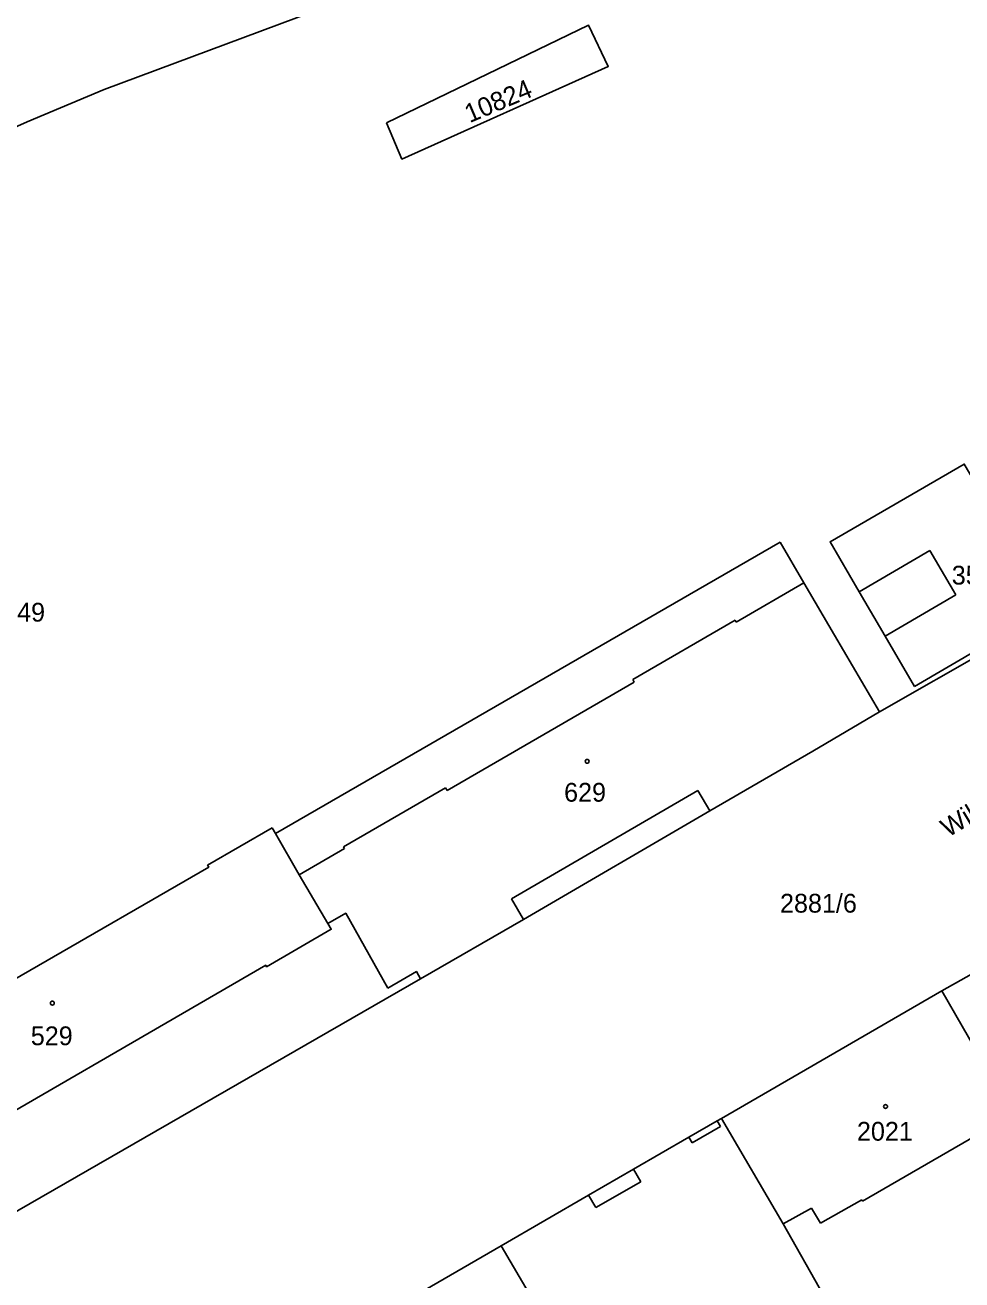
# Model space of a CAD drawing. Extents: x -564952 to -564307, y -1202373 to -1201847.
# Drawn here: x -564730.1 to -564645.4, y -1202200.5 to -1202086.9 of the extents above; entities that cross this region are included whole.
import ezdxf

# ---------------------------------------------------------------- set-up
doc = ezdxf.new("R2010")
doc.units = 0
for name, color, linetype in [('Hranice parcel', 7, 'Continuous'), ('Parcelní čísla', 7, 'Continuous'), ('Pop  PČ popisy', 7, 'Continuous'), ('Vnitřní kresba', 7, 'Continuous'), ('Značky budov', 7, 'Continuous')]:
    doc.layers.add(name, color=color, linetype=linetype)

msp = doc.modelspace()

# ---------------------------------------------------------------- linework, layer by layer
at = {"layer": 'Hranice parcel'}
for p, q in [((-564707.49, -1202160.1), (-564661.83, -1202133.72)), ((-564634.78, -1202138.78), (-564652.84, -1202149.09)), ((-564656.9, -1202142.15), (-564652.84, -1202149.09)), ((-564652.84, -1202149.09), (-564658.86, -1202152.65)), ((-564707.79, -1202159.58), (-564707.49, -1202160.1)), ((-564647.18, -1202174.34), (-564629.78, -1202164.5)), ((-564667.14, -1202185.87), (-564647.18, -1202174.34)), ((-564667.14, -1202185.87), (-564661.56, -1202195.43)), ((-564694.52, -1202201.73), (-564687.07, -1202197.41))]:
    msp.add_line(p, q, dxfattribs=at)
for points in [[(-564637.69, -1202058.81), (-564638.03, -1202059.06), (-564655, -1202066.79), (-564662.43, -1202069.69), (-564704.06, -1202085.69), (-564722.99, -1202092.74), (-564729.95, -1202095.67), (-564736.84, -1202098.72), (-564741.32, -1202100.95), (-564768.52, -1202116.71), (-564777.25, -1202121.88), (-564783.74, -1202125.64), (-564785.97, -1202126.79), (-564816.39, -1202144.49)], [(-564697.44, -1202095.78), (-564679.17, -1202086.93), (-564677.37, -1202090.67), (-564696.04, -1202099.05), (-564697.44, -1202095.78)], [(-564649.66, -1202146.78), (-564652.32, -1202142.22), (-564654.66, -1202138.21), (-564657.3, -1202133.69), (-564645.16, -1202126.66), (-564637.48, -1202139.67), (-564649.66, -1202146.78)], [(-564661.83, -1202133.72), (-564659.67, -1202137.41), (-564656.9, -1202142.15)], [(-564658.86, -1202152.65), (-564668.19, -1202158.04), (-564685.03, -1202167.87), (-564694.35, -1202173.24)], [(-564746.42, -1202194.29), (-564751.8, -1202185.07), (-564746.02, -1202181.72), (-564745.95, -1202181.85), (-564713.53, -1202163.13), (-564713.63, -1202162.96), (-564707.79, -1202159.58)], [(-564702.76, -1202168.23), (-564705.33, -1202163.82), (-564707.49, -1202160.1)], [(-564746.42, -1202194.29), (-564740.54, -1202190.88), (-564740.63, -1202190.71), (-564708.37, -1202172.01), (-564708.29, -1202172.15), (-564702.44, -1202168.76), (-564702.76, -1202168.23)], [(-564702.76, -1202168.23), (-564701.13, -1202167.31), (-564697.31, -1202174.08)], [(-564697.31, -1202174.08), (-564694.74, -1202172.59), (-564694.35, -1202173.24)], [(-564694.35, -1202173.24), (-564735.89, -1202197.13), (-564730.32, -1202210.59), (-564747.11, -1202220.56)], [(-564647.18, -1202174.34), (-564641.67, -1202183.91), (-564640.9, -1202185.58), (-564639.75, -1202188.35)], [(-564687.07, -1202197.41), (-564679.15, -1202192.82), (-564675.09, -1202190.47), (-564670.07, -1202187.57), (-564667.53, -1202186.1), (-564667.14, -1202185.87)], [(-564661.56, -1202195.43), (-564657.9, -1202201.87), (-564654.13, -1202208.52)], [(-564675.55, -1202217.24), (-564682.1, -1202205.88), (-564687.07, -1202197.41)]]:
    msp.add_lwpolyline(points, dxfattribs=at)
at = {"layer": 'Vnitřní kresba'}
for p, q in [((-564654.66, -1202138.21), (-564648.27, -1202134.48)), ((-564648.27, -1202134.48), (-564645.93, -1202138.49)), ((-564659.67, -1202137.41), (-564665.8, -1202140.95)), ((-564645.93, -1202138.49), (-564652.32, -1202142.22)), ((-564665.9, -1202140.78), (-564675.16, -1202146.16)), ((-564665.8, -1202140.95), (-564665.9, -1202140.78)), ((-564675.02, -1202146.39), (-564691.95, -1202156.19)), ((-564675.16, -1202146.16), (-564675.02, -1202146.39)), ((-564692.09, -1202155.95), (-564701.33, -1202161.3)), ((-564691.95, -1202156.19), (-564692.09, -1202155.95)), ((-564669.27, -1202156.19), (-564686.12, -1202166.01)), ((-564668.19, -1202158.04), (-564669.27, -1202156.19)), ((-564701.24, -1202161.46), (-564705.33, -1202163.82)), ((-564701.33, -1202161.3), (-564701.24, -1202161.46)), ((-564686.12, -1202166.01), (-564685.03, -1202167.87)), ((-564667.23, -1202186.62), (-564667.53, -1202186.1)), ((-564654.37, -1202193.36), (-564640.9, -1202185.58)), ((-564670.07, -1202187.57), (-564669.77, -1202188.09)), ((-564669.77, -1202188.09), (-564667.23, -1202186.62)), ((-564674.44, -1202191.6), (-564675.09, -1202190.47)), ((-564678.49, -1202193.95), (-564674.44, -1202191.6)), ((-564679.15, -1202192.82), (-564678.49, -1202193.95)), ((-564658.17, -1202195.36), (-564654.44, -1202193.24)), ((-564654.44, -1202193.24), (-564654.37, -1202193.36)), ((-564661.56, -1202195.43), (-564658.98, -1202193.99)), ((-564658.98, -1202193.99), (-564658.17, -1202195.36))]:
    msp.add_line(p, q, dxfattribs=at)
at = {"layer": 'Značky budov'}
for centre in [(-564679.28, -1202153.56), (-564727.68, -1202175.44), (-564652.28, -1202184.8)]:
    msp.add_circle(centre, 0.175, dxfattribs=at)

# ---------------------------------------------------------------- texts
at = {"layer": 'Parcelní čísla'}
msp.add_text('10824', height=1.7, rotation=23, dxfattribs=at).set_placement((-564689.92, -1202095.81))
for s, p in [('3560', (-564646.29, -1202137.56)), ('2864/649', (-564737.82, -1202140.91)), ('629', (-564681.37, -1202157.21)), ('2881/6', (-564661.83, -1202167.25)), ('529', (-564729.63, -1202179.25)), ('2021', (-564654.87, -1202187.89))]:
    msp.add_text(s, height=1.7, dxfattribs=at).set_placement(p)
at = {"layer": 'Pop  PČ popisy'}
msp.add_text('Wilsonova', height=1.7, rotation=31, dxfattribs=at).set_placement((-564646.62, -1202160.48))

doc.saveas('drawing.dxf')
